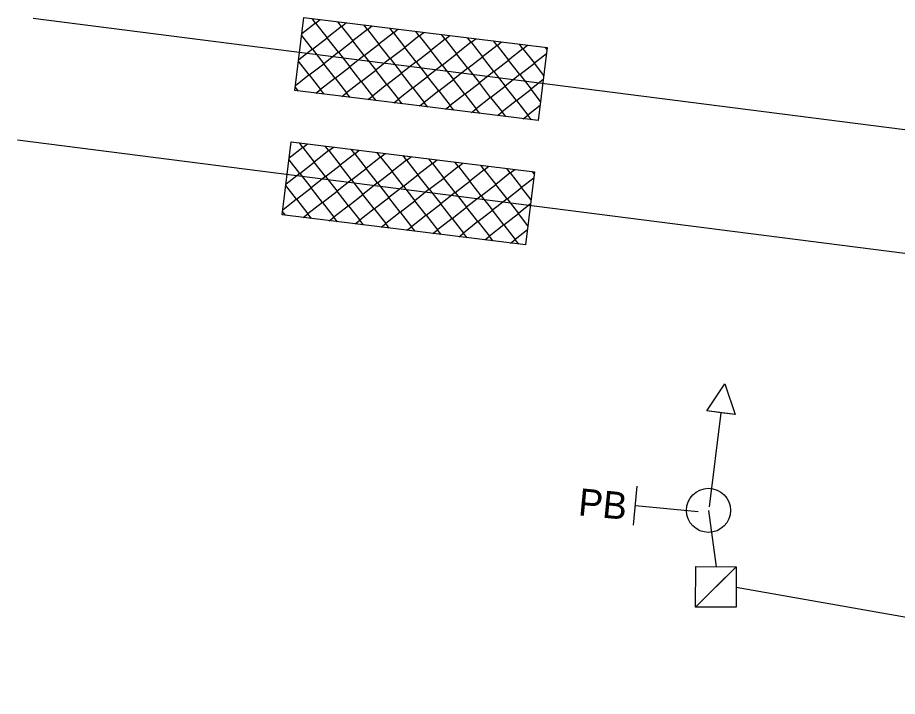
# Model space of a CAD drawing. Extents: x -200 to 1730068, y -325 to 756043.
# Drawn here: x 1725346.1 to 1725417.9, y 658568.5 to 658623.8 of the extents above; entities that cross this region are included whole.
import ezdxf

# ---------------------------------------------------------------- set-up
doc = ezdxf.new("R2010")
doc.units = 0
for name, color, linetype in [('DESIGN - SCRATCH - User 3', 7, 'Continuous'), ('DESIGN - TRAFFIC CONTROL PERMANENT - Signalization', 7, 'Continuous'), ('SURVEY - TRAFFIC CONTROL - Signs and Devices with Text', 7, 'Continuous')]:
    doc.layers.add(name, color=color, linetype=linetype)

msp = doc.modelspace()

# ---------------------------------------------------------------- linework, layer by layer
at = {"layer": 'DESIGN - SCRATCH - User 3'}
for p, q in [((1725347.363, 658623.784), (1725468.697, 658608.266)), ((1725346.094, 658613.864), (1725468.98, 658598.148))]:
    msp.add_line(p, q, dxfattribs=at)
at = {"layer": 'DESIGN - TRAFFIC CONTROL PERMANENT - Signalization'}
for p, q in [((1725370.404, 658623.376), (1725369.287, 658622.495)), ((1725370.404, 658623.376), (1725370.115, 658623.746)), ((1725370.404, 658623.376), (1725370.777, 658623.664)), ((1725370.404, 658623.376), (1725371.335, 658622.183)), ((1725372.518, 658623.115), (1725372.229, 658623.485)), ((1725372.518, 658623.115), (1725372.891, 658623.404)), ((1725372.518, 658623.115), (1725371.335, 658622.183)), ((1725372.518, 658623.115), (1725373.449, 658621.922)), ((1725374.632, 658622.855), (1725373.449, 658621.922)), ((1725374.632, 658622.855), (1725374.343, 658623.225)), ((1725374.632, 658622.855), (1725375.005, 658623.143)), ((1725374.632, 658622.855), (1725375.563, 658621.662)), ((1725376.746, 658622.595), (1725376.457, 658622.965)), ((1725376.746, 658622.595), (1725377.119, 658622.883)), ((1725378.86, 658622.334), (1725378.571, 658622.704)), ((1725378.86, 658622.334), (1725379.233, 658622.623)), ((1725370.144, 658621.262), (1725369.272, 658622.378)), ((1725370.144, 658621.262), (1725371.335, 658622.183)), ((1725372.258, 658621.001), (1725371.335, 658622.183)), ((1725372.258, 658621.001), (1725373.449, 658621.922)), ((1725374.372, 658620.741), (1725373.449, 658621.922)), ((1725376.746, 658622.595), (1725375.563, 658621.662)), ((1725376.746, 658622.595), (1725377.677, 658621.402)), ((1725378.86, 658622.334), (1725377.677, 658621.402)), ((1725378.86, 658622.334), (1725379.791, 658621.141)), ((1725380.974, 658622.074), (1725379.791, 658621.141)), ((1725380.974, 658622.074), (1725380.685, 658622.444)), ((1725380.974, 658622.074), (1725381.347, 658622.362)), ((1725380.974, 658622.074), (1725381.905, 658620.881)), ((1725383.088, 658621.814), (1725382.799, 658622.184)), ((1725383.088, 658621.814), (1725383.461, 658622.102)), ((1725385.202, 658621.553), (1725384.913, 658621.923)), ((1725370.144, 658621.262), (1725369.026, 658620.381)), ((1725370.144, 658621.262), (1725371.075, 658620.069)), ((1725374.372, 658620.741), (1725375.563, 658621.662)), ((1725376.486, 658620.481), (1725375.563, 658621.662)), ((1725376.486, 658620.481), (1725377.677, 658621.402)), ((1725378.6, 658620.22), (1725377.677, 658621.402)), ((1725383.088, 658621.814), (1725381.905, 658620.881)), ((1725383.088, 658621.814), (1725384.019, 658620.621)), ((1725385.202, 658621.553), (1725384.019, 658620.621)), ((1725385.202, 658621.553), (1725385.575, 658621.842)), ((1725385.202, 658621.553), (1725386.133, 658620.36)), ((1725387.316, 658621.293), (1725386.133, 658620.36)), ((1725387.316, 658621.293), (1725387.027, 658621.663)), ((1725387.316, 658621.293), (1725387.689, 658621.581)), ((1725387.316, 658621.293), (1725388.247, 658620.1)), ((1725389.281, 658621.223), (1725389.141, 658621.403)), ((1725372.258, 658621.001), (1725371.075, 658620.069)), ((1725372.258, 658621.001), (1725373.189, 658619.808)), ((1725374.372, 658620.741), (1725373.189, 658619.808)), ((1725374.372, 658620.741), (1725375.303, 658619.548)), ((1725376.486, 658620.481), (1725375.303, 658619.548)), ((1725376.486, 658620.481), (1725377.417, 658619.288)), ((1725378.6, 658620.22), (1725379.791, 658621.141)), ((1725380.714, 658619.96), (1725379.791, 658621.141)), ((1725380.714, 658619.96), (1725381.905, 658620.881)), ((1725382.828, 658619.7), (1725381.905, 658620.881)), ((1725382.828, 658619.7), (1725384.019, 658620.621)), ((1725384.942, 658619.439), (1725384.019, 658620.621)), ((1725389.239, 658620.882), (1725388.247, 658620.1)), ((1725369.883, 658619.148), (1725369.012, 658620.263)), ((1725369.883, 658619.148), (1725371.075, 658620.069)), ((1725371.997, 658618.887), (1725371.075, 658620.069)), ((1725371.997, 658618.887), (1725373.189, 658619.808)), ((1725374.111, 658618.627), (1725373.189, 658619.808)), ((1725378.6, 658620.22), (1725377.417, 658619.288)), ((1725378.6, 658620.22), (1725379.531, 658619.027)), ((1725380.714, 658619.96), (1725379.531, 658619.027)), ((1725380.714, 658619.96), (1725381.645, 658618.767)), ((1725384.942, 658619.439), (1725386.133, 658620.36)), ((1725387.056, 658619.179), (1725386.133, 658620.36)), ((1725387.056, 658619.179), (1725388.247, 658620.1)), ((1725389.021, 658619.109), (1725388.247, 658620.1)), ((1725369.883, 658619.148), (1725368.766, 658618.267)), ((1725369.883, 658619.148), (1725370.814, 658617.955)), ((1725374.111, 658618.627), (1725375.303, 658619.548)), ((1725376.225, 658618.367), (1725375.303, 658619.548)), ((1725376.225, 658618.367), (1725377.417, 658619.288)), ((1725378.339, 658618.106), (1725377.417, 658619.288)), ((1725378.339, 658618.106), (1725379.531, 658619.027)), ((1725380.453, 658617.846), (1725379.531, 658619.027)), ((1725382.828, 658619.7), (1725381.645, 658618.767)), ((1725382.828, 658619.7), (1725383.759, 658618.507)), ((1725384.942, 658619.439), (1725383.759, 658618.507)), ((1725384.942, 658619.439), (1725385.873, 658618.246)), ((1725387.056, 658619.179), (1725385.873, 658618.246)), ((1725387.056, 658619.179), (1725387.987, 658617.986)), ((1725371.997, 658618.887), (1725370.814, 658617.955)), ((1725371.997, 658618.887), (1725372.928, 658617.694)), ((1725374.111, 658618.627), (1725372.928, 658617.694)), ((1725374.111, 658618.627), (1725375.043, 658617.434)), ((1725376.225, 658618.367), (1725375.043, 658617.434)), ((1725376.225, 658618.367), (1725377.157, 658617.174)), ((1725380.453, 658617.846), (1725381.645, 658618.767)), ((1725382.567, 658617.586), (1725381.645, 658618.767)), ((1725382.567, 658617.586), (1725383.759, 658618.507)), ((1725384.681, 658617.325), (1725383.759, 658618.507)), ((1725388.979, 658618.768), (1725387.987, 658617.986)), ((1725368.995, 658617.838), (1725368.752, 658618.149)), ((1725370.434, 658617.661), (1725370.814, 658617.955)), ((1725371.109, 658617.578), (1725370.814, 658617.955)), ((1725372.548, 658617.401), (1725372.928, 658617.694)), ((1725373.223, 658617.318), (1725372.928, 658617.694)), ((1725378.339, 658618.106), (1725377.157, 658617.174)), ((1725378.339, 658618.106), (1725379.271, 658616.913)), ((1725380.453, 658617.846), (1725379.271, 658616.913)), ((1725380.453, 658617.846), (1725381.385, 658616.653)), ((1725382.567, 658617.586), (1725381.385, 658616.653)), ((1725382.567, 658617.586), (1725383.499, 658616.393)), ((1725384.681, 658617.325), (1725385.873, 658618.246)), ((1725386.796, 658617.065), (1725385.873, 658618.246)), ((1725386.796, 658617.065), (1725387.987, 658617.986)), ((1725388.761, 658616.995), (1725387.987, 658617.986)), ((1725374.662, 658617.14), (1725375.043, 658617.434)), ((1725375.337, 658617.057), (1725375.043, 658617.434)), ((1725376.776, 658616.88), (1725377.157, 658617.174)), ((1725377.451, 658616.797), (1725377.157, 658617.174)), ((1725378.891, 658616.62), (1725379.271, 658616.913)), ((1725379.565, 658616.537), (1725379.271, 658616.913)), ((1725384.681, 658617.325), (1725383.499, 658616.393)), ((1725384.681, 658617.325), (1725385.613, 658616.132)), ((1725386.796, 658617.065), (1725385.613, 658616.132)), ((1725386.796, 658617.065), (1725387.727, 658615.872)), ((1725381.005, 658616.359), (1725381.385, 658616.653)), ((1725381.679, 658616.276), (1725381.385, 658616.653)), ((1725383.119, 658616.099), (1725383.499, 658616.393)), ((1725383.793, 658616.016), (1725383.499, 658616.393)), ((1725388.719, 658616.654), (1725387.727, 658615.872)), ((1725385.233, 658615.839), (1725385.613, 658616.132)), ((1725385.907, 658615.756), (1725385.613, 658616.132)), ((1725387.347, 658615.578), (1725387.727, 658615.872)), ((1725388.021, 658615.495), (1725387.727, 658615.872)), ((1725388.568, 658615.428), (1725388.568, 658615.428)), ((1725369.367, 658613.24), (1725369.078, 658613.61)), ((1725369.367, 658613.24), (1725369.74, 658613.529)), ((1725371.481, 658612.98), (1725371.192, 658613.35)), ((1725369.367, 658613.24), (1725368.25, 658612.359)), ((1725369.367, 658613.24), (1725370.298, 658612.047)), ((1725371.481, 658612.98), (1725370.298, 658612.047)), ((1725371.481, 658612.98), (1725371.854, 658613.268)), ((1725371.481, 658612.98), (1725372.412, 658611.787)), ((1725373.595, 658612.719), (1725372.412, 658611.787)), ((1725373.595, 658612.719), (1725373.306, 658613.089)), ((1725373.595, 658612.719), (1725373.968, 658613.008)), ((1725373.595, 658612.719), (1725374.526, 658611.527)), ((1725375.709, 658612.459), (1725375.42, 658612.829)), ((1725375.709, 658612.459), (1725376.082, 658612.748)), ((1725377.823, 658612.199), (1725377.534, 658612.569)), ((1725369.107, 658611.126), (1725368.235, 658612.242)), ((1725369.107, 658611.126), (1725370.298, 658612.047)), ((1725371.221, 658610.866), (1725370.298, 658612.047)), ((1725375.709, 658612.459), (1725374.526, 658611.527)), ((1725375.709, 658612.459), (1725376.64, 658611.266)), ((1725377.823, 658612.199), (1725376.64, 658611.266)), ((1725377.823, 658612.199), (1725378.196, 658612.487)), ((1725377.823, 658612.199), (1725378.754, 658611.006)), ((1725379.937, 658611.938), (1725378.754, 658611.006)), ((1725379.937, 658611.938), (1725379.648, 658612.308)), ((1725379.937, 658611.938), (1725380.31, 658612.227)), ((1725379.937, 658611.938), (1725380.868, 658610.746)), ((1725382.051, 658611.678), (1725381.762, 658612.048)), ((1725382.051, 658611.678), (1725382.424, 658611.967)), ((1725369.107, 658611.126), (1725367.989, 658610.245)), ((1725369.107, 658611.126), (1725370.038, 658609.933)), ((1725371.221, 658610.866), (1725372.412, 658611.787)), ((1725373.335, 658610.605), (1725372.412, 658611.787)), ((1725373.335, 658610.605), (1725374.526, 658611.527)), ((1725375.449, 658610.345), (1725374.526, 658611.527)), ((1725375.449, 658610.345), (1725376.64, 658611.266)), ((1725377.563, 658610.085), (1725376.64, 658611.266)), ((1725382.051, 658611.678), (1725380.868, 658610.746)), ((1725382.051, 658611.678), (1725382.982, 658610.485)), ((1725384.165, 658611.418), (1725382.982, 658610.485)), ((1725384.165, 658611.418), (1725383.876, 658611.788)), ((1725384.165, 658611.418), (1725384.538, 658611.706)), ((1725384.165, 658611.418), (1725385.096, 658610.225)), ((1725386.279, 658611.157), (1725385.096, 658610.225)), ((1725386.279, 658611.157), (1725385.99, 658611.527)), ((1725386.279, 658611.157), (1725386.652, 658611.446)), ((1725386.279, 658611.157), (1725387.21, 658609.965)), ((1725388.244, 658611.088), (1725388.104, 658611.267)), ((1725371.221, 658610.866), (1725370.038, 658609.933)), ((1725371.221, 658610.866), (1725372.152, 658609.673)), ((1725373.335, 658610.605), (1725372.152, 658609.673)), ((1725373.335, 658610.605), (1725374.266, 658609.413)), ((1725377.563, 658610.085), (1725378.754, 658611.006)), ((1725379.677, 658609.824), (1725378.754, 658611.006)), ((1725379.677, 658609.824), (1725380.868, 658610.746)), ((1725381.791, 658609.564), (1725380.868, 658610.746)), ((1725381.791, 658609.564), (1725382.982, 658610.485)), ((1725383.905, 658609.304), (1725382.982, 658610.485)), ((1725388.202, 658610.747), (1725387.21, 658609.965)), ((1725368.846, 658609.012), (1725367.975, 658610.128)), ((1725368.846, 658609.012), (1725370.038, 658609.933)), ((1725370.96, 658608.752), (1725370.038, 658609.933)), ((1725375.449, 658610.345), (1725374.266, 658609.413)), ((1725375.449, 658610.345), (1725376.38, 658609.152)), ((1725377.563, 658610.085), (1725376.38, 658609.152)), ((1725377.563, 658610.085), (1725378.494, 658608.892)), ((1725379.677, 658609.824), (1725378.494, 658608.892)), ((1725379.677, 658609.824), (1725380.608, 658608.632)), ((1725383.905, 658609.304), (1725385.096, 658610.225)), ((1725386.019, 658609.043), (1725385.096, 658610.225)), ((1725386.019, 658609.043), (1725387.21, 658609.965)), ((1725387.984, 658608.974), (1725387.21, 658609.965)), ((1725368.846, 658609.012), (1725367.729, 658608.131)), ((1725368.846, 658609.012), (1725369.777, 658607.819)), ((1725370.96, 658608.752), (1725372.152, 658609.673)), ((1725373.074, 658608.491), (1725372.152, 658609.673)), ((1725373.074, 658608.491), (1725374.266, 658609.413)), ((1725375.188, 658608.231), (1725374.266, 658609.413)), ((1725375.188, 658608.231), (1725376.38, 658609.152)), ((1725377.302, 658607.971), (1725376.38, 658609.152)), ((1725381.791, 658609.564), (1725380.608, 658608.632)), ((1725381.791, 658609.564), (1725382.722, 658608.371)), ((1725383.905, 658609.304), (1725382.722, 658608.371)), ((1725383.905, 658609.304), (1725384.836, 658608.111)), ((1725386.019, 658609.043), (1725384.836, 658608.111)), ((1725386.019, 658609.043), (1725386.95, 658607.851)), ((1725370.96, 658608.752), (1725369.777, 658607.819)), ((1725370.96, 658608.752), (1725371.891, 658607.559)), ((1725373.074, 658608.491), (1725371.891, 658607.559)), ((1725373.074, 658608.491), (1725374.005, 658607.299)), ((1725377.302, 658607.971), (1725378.494, 658608.892)), ((1725379.416, 658607.71), (1725378.494, 658608.892)), ((1725379.416, 658607.71), (1725380.608, 658608.632)), ((1725381.53, 658607.45), (1725380.608, 658608.632)), ((1725381.53, 658607.45), (1725382.722, 658608.371)), ((1725383.644, 658607.19), (1725382.722, 658608.371)), ((1725387.942, 658608.633), (1725386.95, 658607.851)), ((1725367.958, 658607.703), (1725367.715, 658608.014)), ((1725369.397, 658607.525), (1725369.777, 658607.819)), ((1725370.072, 658607.442), (1725369.777, 658607.819)), ((1725371.511, 658607.265), (1725371.891, 658607.559)), ((1725372.186, 658607.182), (1725371.891, 658607.559)), ((1725375.188, 658608.231), (1725374.005, 658607.299)), ((1725375.188, 658608.231), (1725376.12, 658607.038)), ((1725377.302, 658607.971), (1725376.12, 658607.038)), ((1725377.302, 658607.971), (1725378.234, 658606.778)), ((1725379.416, 658607.71), (1725378.234, 658606.778)), ((1725379.416, 658607.71), (1725380.348, 658606.518)), ((1725383.644, 658607.19), (1725384.836, 658608.111)), ((1725385.758, 658606.929), (1725384.836, 658608.111)), ((1725385.758, 658606.929), (1725386.95, 658607.851)), ((1725387.724, 658606.86), (1725386.95, 658607.851)), ((1725373.625, 658607.005), (1725374.005, 658607.299)), ((1725374.3, 658606.922), (1725374.005, 658607.299)), ((1725375.739, 658606.744), (1725376.12, 658607.038)), ((1725376.414, 658606.661), (1725376.12, 658607.038)), ((1725381.53, 658607.45), (1725380.348, 658606.518)), ((1725381.53, 658607.45), (1725382.462, 658606.257)), ((1725383.644, 658607.19), (1725382.462, 658606.257)), ((1725383.644, 658607.19), (1725384.576, 658605.997)), ((1725385.758, 658606.929), (1725384.576, 658605.997)), ((1725385.758, 658606.929), (1725386.69, 658605.737)), ((1725377.853, 658606.484), (1725378.234, 658606.778)), ((1725378.528, 658606.401), (1725378.234, 658606.778)), ((1725379.968, 658606.224), (1725380.348, 658606.518)), ((1725380.642, 658606.141), (1725380.348, 658606.518)), ((1725382.082, 658605.963), (1725382.462, 658606.257)), ((1725382.756, 658605.88), (1725382.462, 658606.257)), ((1725387.682, 658606.518), (1725386.69, 658605.737)), ((1725384.196, 658605.703), (1725384.576, 658605.997)), ((1725384.87, 658605.62), (1725384.576, 658605.997)), ((1725386.31, 658605.443), (1725386.69, 658605.737)), ((1725386.984, 658605.36), (1725386.69, 658605.737)), ((1725387.531, 658605.292), (1725387.531, 658605.292)), ((1725396.335, 658582.426), (1725396.645, 658585.606)), ((1725401.596, 658583.517), (1725396.49, 658584.016)), ((1725402.455, 658583.646), (1725403.066, 658579.047)), ((1725404.716, 658579.039), (1725401.4, 658575.755)), ((1725403.058, 658577.397), (1725403.058, 658577.397)), ((1725404.708, 658577.389), (1725455.243, 658568.474))]:
    msp.add_line(p, q, dxfattribs=at)
for points in [[(1725369.451, 658623.827), (1725389.301, 658621.383), (1725388.568, 658615.428), (1725368.718, 658617.872)], [(1725368.414, 658613.692), (1725388.264, 658611.247), (1725387.531, 658605.292), (1725367.68, 658607.737)], [(1725404.641, 658591.462), (1725402.319, 658591.751), (1725403.773, 658593.958)], [(1725404.716, 658579.039), (1725404.7, 658575.739), (1725401.4, 658575.755), (1725401.416, 658579.055)], [(1725401.416, 658579.055), (1725404.716, 658579.039), (1725403.058, 658577.397), (1725401.4, 658575.755)]]:
    msp.add_lwpolyline(points, close=True, dxfattribs=at)
msp.add_lwpolyline([(1725402.523, 658583.926), (1725403.48, 658591.606), (1725402.319, 658591.751), (1725403.773, 658593.958), (1725404.641, 658591.462), (1725403.48, 658591.606)], dxfattribs=at)
at = {"layer": 'SURVEY - TRAFFIC CONTROL - Signs and Devices with Text'}
msp.add_line((1725402.455, 658583.646), (1725402.455, 658583.646), dxfattribs=at)
msp.add_circle((1725402.455, 658583.646), 1.8, dxfattribs=at)

# ---------------------------------------------------------------- texts
at = {"layer": 'DESIGN - TRAFFIC CONTROL PERMANENT - Signalization'}
msp.add_text('PB', height=2.2147, rotation=354.42133, dxfattribs=at).set_placement((1725391.766, 658583.251))

doc.saveas('drawing.dxf')
